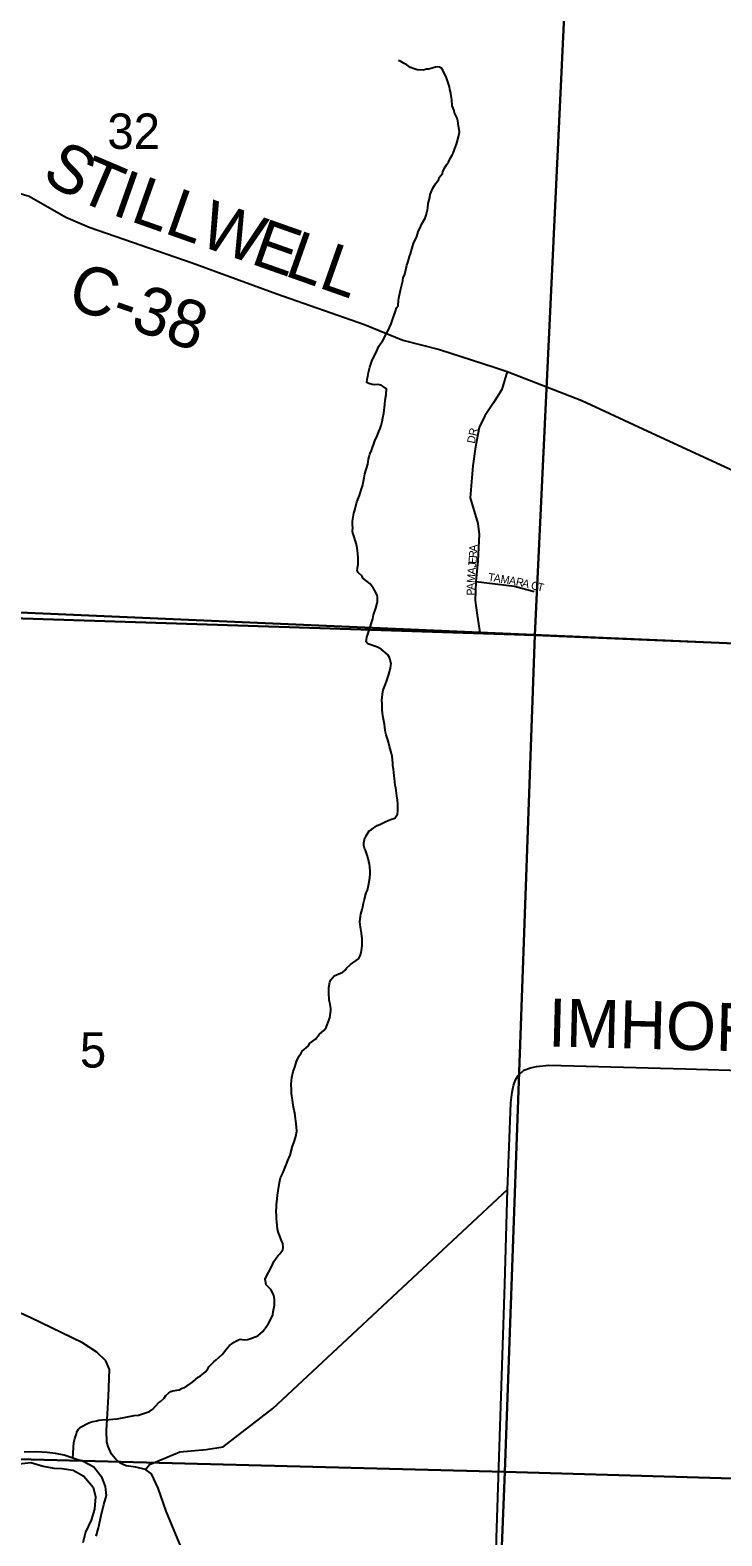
# Model space of a CAD drawing. Extents: x 1310247 to 1552180, y 377264 to 706493.
# Drawn here: x 1322302 to 1326623, y 541170 to 550580 of the extents above; entities that cross this region are included whole.
import ezdxf

# ---------------------------------------------------------------- set-up
doc = ezdxf.new("R2010")
doc.units = 0
for name, color, linetype in [('GM_X_County_Road', 7, 'Continuous'), ('GM_X_County_Road_Text', 7, 'Continuous'), ('GM_X_Major_River', 7, 'Continuous'), ('GM_X_Minor_River', 7, 'Continuous'), ('GM_X_Section', 7, 'Continuous'), ('GM_X_Section_Text', 7, 'Continuous'), ('GM_X_Township', 7, 'Continuous'), ('GM_X_Township_Road', 7, 'Continuous'), ('GM_X_Township_Road_Text', 7, 'Continuous'), ('GM_X_Township_ROW', 7, 'Continuous'), ('GM_X_Township_Subdivision', 7, 'Continuous'), ('GM_X_Township_Subdivision_Text', 7, 'Continuous')]:
    doc.layers.add(name, color=color, linetype=linetype)

msp = doc.modelspace()

# ---------------------------------------------------------------- linework, layer by layer
at = {"layer": 'GM_X_County_Road'}
for points in [[(1322096.4, 549601.3), (1322294.8, 549543.1), (1322525.5, 549411.9), (1322670, 549349.5), (1323313, 549125.9), (1323842.5, 548931.7), (1324390.2, 548741), (1324629.9, 548641.7), (1324858.8, 548584.8), (1325200.3, 548474.4), (1325281.8, 548446.6), (1325748.4, 548265.1), (1326187.6, 548062.2), (1326910.4, 547727.8)], [(1323254.6, 541075.1), (1323210.9, 541178.2), (1323151.5, 541324.3), (1323101.1, 541468.2), (1323059.6, 541557.3), (1323023.4, 541584.4), (1322962.2, 541600), (1322902.3, 541608.1), (1322864.8, 541625.3), (1322834.3, 541652.4), (1322810, 541680.9), (1322788.4, 541727.8), (1322781.7, 541755.6), (1322779.6, 541828.2), (1322785.9, 541931.9), (1322791.1, 542040.8), (1322798.3, 542210.9), (1322775.5, 542263.8), (1322718.5, 542318.8), (1322629.2, 542375.8), (1322306.7, 542533.5), (1321975.8, 542680.7)]]:
    msp.add_lwpolyline(points, dxfattribs=at)
at = {"layer": 'GM_X_Major_River'}
for points in [[(1322713.9, 541169.1), (1322729.3, 541220.9), (1322745.3, 541296.7), (1322763.1, 541366.5), (1322778.5, 541422.3), (1322772, 541478.6), (1322751.3, 541533.3), (1322698.9, 541598.8), (1322633.6, 541634.5), (1322568, 541656.2), (1322514.3, 541673.6), (1322460.5, 541684.9), (1322408.5, 541692.2), (1322340.4, 541695.9), (1322264.2, 541693.8)], [(1322232.2, 541620.3), (1322306.6, 541628.5), (1322382.2, 541606.6), (1322450.1, 541592.9), (1322500.2, 541591.7), (1322570, 541579.9), (1322637.3, 541544.2), (1322695.7, 541474.5), (1322710.2, 541414), (1322704.2, 541337.9), (1322682.4, 541268.2), (1322648.3, 541192.8), (1322630.6, 541127)]]:
    msp.add_lwpolyline(points, dxfattribs=at)
at = {"layer": 'GM_X_Minor_River'}
for points in [[(1324599.7, 548858), (1324602.5, 548892), (1324604.9, 548906), (1324616.1, 548955.9), (1324629.4, 549013.7), (1324631.9, 549033.7), (1324640.3, 549049.5), (1324646.8, 549071.4), (1324653.8, 549111.3), (1324660.2, 549127.2), (1324671.1, 549165.1), (1324677.5, 549182.9), (1324690.6, 549226.8), (1324697.1, 549246.6), (1324716.2, 549290.3), (1324720.6, 549306.2), (1324724.9, 549320.2), (1324741.8, 549355.8), (1324748.1, 549369.7), (1324769, 549405.3), (1324775.5, 549423.2), (1324784.3, 549457), (1324786.6, 549469), (1324787.2, 549497.1), (1324798.2, 549534.9), (1324800.6, 549552.9), (1324817.6, 549592.6), (1324834.3, 549620.2), (1324855, 549647.8), (1324857.3, 549659.8), (1324878, 549685.3), (1324880.2, 549697.3), (1324897, 549727), (1324903.3, 549738.8), (1324915.7, 549754.6), (1324928.4, 549782.3), (1324938.8, 549798.1), (1324943.1, 549812), (1324951.7, 549833.9), (1324964.5, 549867.7), (1324968.8, 549881.6), (1324977.6, 549913.5), (1324984.4, 549945.4), (1324975.6, 549997.8), (1324973.9, 550013.8), (1324968.3, 550030), (1324953, 550062.5), (1324951.3, 550078.6), (1324937.9, 550107), (1324934.8, 550145.2), (1324933.1, 550157.2), (1324929.7, 550183.4), (1324927.9, 550195.5), (1324924.3, 550209.6), (1324920.6, 550225.7), (1324915, 550243.9), (1324907.6, 550270.2), (1324900, 550288.4), (1324892.3, 550302.7), (1324880.7, 550325), (1324871.1, 550343.3), (1324859.2, 550349.6), (1324845.2, 550349.9), (1324833.1, 550348.2), (1324819, 550344.6), (1324792.7, 550337.2), (1324778.6, 550335.5), (1324758.4, 550330), (1324718.3, 550333), (1324700.3, 550337.5), (1324678.4, 550346.1), (1324654.7, 550362.7), (1324638.9, 550371.1), (1324617.1, 550383.7), (1324603.2, 550390.1)], [(1324520.1, 546204.8), (1324514.9, 546243), (1324504.1, 546295.4), (1324500.9, 546331.6), (1324499.8, 546369.7), (1324498.4, 546393.8), (1324505.6, 546447.8), (1324510, 546461.7), (1324520.8, 546493.5), (1324527.2, 546509.4), (1324540.1, 546547.2), (1324553.2, 546593), (1324555.6, 546609), (1324555.9, 546623), (1324550.3, 546643.2), (1324546.7, 546659.4), (1324537, 546675.7), (1324507.5, 546700.4), (1324493.7, 546710.8), (1324471.9, 546723.4), (1324412.1, 546744.9), (1324400.4, 546757.3), (1324405.1, 546787.2), (1324418, 546825), (1324441.9, 546900.6), (1324446.5, 546926.6), (1324461.5, 546968.3), (1324470.2, 546998.2), (1324472.5, 547010.2), (1324471.1, 547036.3), (1324469.4, 547048.3), (1324452.1, 547080.9), (1324444.4, 547095.1), (1324424.9, 547119.6), (1324379.5, 547154.9), (1324375.8, 547167), (1324350.2, 547191.7), (1324344.5, 547203.9), (1324346.8, 547215.8), (1324351.4, 547243.8), (1324350.4, 547283.9), (1324348.9, 547308), (1324347.4, 547328.1), (1324342, 547358.3), (1324334.7, 547386.6), (1324323.4, 547419), (1324317.8, 547437.2), (1324316.1, 547451.2), (1324316.5, 547469.3), (1324315, 547489.4), (1324315.5, 547511.4), (1324317.8, 547523.4), (1324324.7, 547561.3), (1324329.1, 547581.3), (1324342.4, 547633.1), (1324359.4, 547672.8), (1324365.9, 547692.7), (1324372.4, 547714.6), (1324376.8, 547730.5), (1324388, 547782.4), (1324392.6, 547808.3), (1324410.1, 547868), (1324412.4, 547882), (1324414.8, 547898), (1324419.2, 547913.9), (1324423.6, 547929.9), (1324434.2, 547953.7), (1324455.6, 548013.3), (1324468.4, 548045.1), (1324479.1, 548070.9), (1324487.6, 548090.7), (1324494, 548108.6), (1324500.6, 548134.5), (1324505.1, 548156.5), (1324511.9, 548186.4), (1324517.1, 548240.4), (1324519.8, 548268.4), (1324524.6, 548302.4), (1324527.4, 548338.4), (1324507.7, 548352.9), (1324493.8, 548361.3), (1324473.9, 548365.8), (1324453.7, 548364.3), (1324437.7, 548366.7), (1324417.8, 548371.2), (1324403.9, 548377.6), (1324406.4, 548399.6), (1324410.8, 548415.5), (1324415.4, 548441.5), (1324424.1, 548473.3), (1324437.1, 548511.1), (1324466.7, 548576.5), (1324479.4, 548604.3), (1324506.5, 548645.8), (1324525.3, 548679.4), (1324535.8, 548699.2), (1324556.9, 548744.8), (1324565.6, 548770.6), (1324582.9, 548824.3), (1324589.4, 548844.2), (1324599.7, 548858)], [(1323959.8, 543776), (1323954.6, 543814.3), (1323950.9, 543828.4), (1323945.7, 543860.6), (1323940.4, 543894.8), (1323937, 543921), (1323935.3, 543935.1), (1323933.8, 543955.2), (1323932.7, 543993.3), (1323935.7, 544035.4), (1323944.6, 544073.2), (1323955.2, 544099), (1323961.7, 544120.9), (1323966.1, 544134.9), (1323983, 544170.5), (1323993.3, 544182.3), (1324001.7, 544200.2), (1324040.6, 544233.3), (1324047, 544247.2), (1324083.8, 544274.3), (1324106.5, 544303.8), (1324139.3, 544331.1), (1324151.7, 544346.8), (1324156.1, 544364.8), (1324173.2, 544408.5), (1324180.3, 544454.4), (1324180.6, 544466.5), (1324175.2, 544492.7), (1324171.5, 544508.8), (1324169.8, 544520.9), (1324166.7, 544561.1), (1324167.2, 544583.1), (1324167.5, 544597.1), (1324174.4, 544631.1), (1324180.7, 544644.9), (1324201.4, 544670.5), (1324254.1, 544693.3), (1324270.4, 544704.9), (1324278.8, 544718.7), (1324303.4, 544740.2), (1324352.4, 544777), (1324362.9, 544794.8), (1324369.4, 544816.7), (1324371.7, 544828.7), (1324376.5, 544860.7), (1324376.7, 544872.7), (1324375.5, 544904.8), (1324373.7, 544916.9), (1324372.2, 544937), (1324365.1, 544975.3), (1324361.8, 545007.4), (1324364.6, 545043.5), (1324366.9, 545055.4), (1324375.6, 545085.3), (1324380, 545101.2), (1324384.6, 545125.2), (1324389, 545141.1), (1324400.1, 545189), (1324408.5, 545204.8), (1324415.2, 545234.7), (1324424.4, 545282.6), (1324425, 545306.7), (1324425.3, 545320.7), (1324424, 545352.8), (1324422.3, 545366.9), (1324413.1, 545403.2), (1324407.6, 545423.4), (1324396.3, 545455.8), (1324390.5, 545468), (1324386.9, 545484.1), (1324385.3, 545502.2), (1324392, 545532.1), (1324400.4, 545546), (1324419.1, 545575.6), (1324433.4, 545585.2), (1324470.2, 545610.4), (1324486.3, 545616), (1324518.9, 545633.3), (1324539.1, 545640.8), (1324553.3, 545646.4), (1324579.6, 545655.8), (1324596.3, 545681.5), (1324598.8, 545701.5), (1324597.7, 545743.6), (1324596.3, 545767.7), (1324592.9, 545795.9), (1324586, 545844.2), (1324582.4, 545862.3), (1324577.3, 545902.5), (1324575.7, 545920.6), (1324570.6, 545960.9), (1324567.2, 545985), (1324567.5, 545999), (1324562.5, 546043.3), (1324558.9, 546059.4), (1324545.9, 546103.9), (1324540.4, 546130.1), (1324536.8, 546144.2), (1324525.5, 546176.6), (1324521.8, 546192.7), (1324520.1, 546204.8)], [(1322568, 541656.2), (1322575.6, 541754.7), (1322580.2, 541778.7), (1322590.9, 541808.5), (1322593.2, 541820.4), (1322603.6, 541836.2), (1322616, 541850), (1322664.8, 541874.8), (1322678.9, 541880.5), (1322693.1, 541884.2), (1322719.3, 541889.5), (1322731.4, 541893.2), (1322751.6, 541894.7), (1322795.8, 541897.7), (1322817.9, 541899.1), (1322846.1, 541902.4), (1322898.5, 541911.1), (1322951, 541921.9), (1322979.2, 541925.2), (1323047.9, 541947.5), (1323068.4, 541963.1), (1323103.4, 542002.3), (1323115.7, 542010), (1323138.2, 542031.5), (1323148.6, 542047.3), (1323169.1, 542064.9), (1323181.4, 542072.6), (1323193.5, 542076.3), (1323217.7, 542081.7), (1323231.8, 542083.4), (1323252.1, 542092.9), (1323268.3, 542098.5), (1323317.3, 542133.4), (1323352.1, 542162.6), (1323366.3, 542170.3), (1323397, 542195.6), (1323411.5, 542213.3), (1323417.8, 542227.2), (1323448.7, 542258.5), (1323463, 542270.2), (1323501.9, 542303.3), (1323533, 542342.6), (1323547.4, 542360.3), (1323576, 542381.7), (1323590.3, 542389.3), (1323602.5, 542395.1), (1323614.6, 542398.8), (1323626.6, 542398.5), (1323640.6, 542396.1), (1323658.7, 542397.7), (1323674.9, 542401.3), (1323723.5, 542420.1), (1323754.3, 542447.4), (1323783.2, 542484.8), (1323791.5, 542496.7), (1323799.9, 542512.5), (1323816.9, 542552.2), (1323819.4, 542570.2), (1323828.4, 542612.1), (1323828.8, 542630.1), (1323827.2, 542648.2), (1323823.8, 542674.3), (1323804.5, 542710.9), (1323777.1, 542739.7), (1323769.9, 542774), (1323776.3, 542789.8), (1323807.7, 542847.2), (1323818.3, 542871), (1323824.6, 542884.9), (1323849.6, 542920.4), (1323861.9, 542932.1), (1323880.5, 542957.7), (1323882.9, 542971.7), (1323879.5, 542997.9), (1323873.7, 543010), (1323868.1, 543026.2), (1323858.6, 543048.5), (1323852.9, 543064.7), (1323847.4, 543086.9), (1323842.4, 543133.2), (1323840.9, 543153.3), (1323841.4, 543173.3), (1323837.9, 543195.4), (1323840.6, 543227.5), (1323840.9, 543239.5), (1323843.8, 543277.5), (1323846.3, 543299.5), (1323851, 543327.5), (1323860.2, 543379.4), (1323864.9, 543407.4), (1323879.6, 543437.1), (1323900.9, 543488.7), (1323911.6, 543516.5), (1323926.4, 543550.2), (1323939.7, 543606.1), (1323948.2, 543625.9), (1323961.2, 543665.7), (1323968, 543699.6), (1323966.6, 543725.7), (1323961.5, 543764), (1323959.8, 543776)]]:
    msp.add_lwpolyline(points, dxfattribs=at)
at = {"layer": 'GM_X_Section'}
for points in [[(1320349.9, 552243.3), (1325704.6, 552080.5), (1325455.2, 546798.8), (1320142.5, 546971.1)], [(1325704.6, 552080.5), (1331016.4, 551943.3), (1330756.7, 546578.8), (1325455.2, 546798.8)], [(1325455.2, 546798.8), (1325267.1, 541570.4), (1319907.5, 541709.9), (1320142.5, 546971.1)], [(1330756.7, 546578.8), (1330462.3, 541419.2), (1325267.1, 541570.4), (1325455.2, 546798.8)], [(1319907.5, 541709.9), (1325267.1, 541570.4), (1325046.7, 536089.3), (1319682.6, 536279.1)], [(1325267.1, 541570.4), (1330462.3, 541419.2), (1330101.6, 535933.3), (1325046.7, 536089.3)]]:
    msp.add_lwpolyline(points, close=True, dxfattribs=at)
at = {"layer": 'GM_X_Township'}
for points in [[(1329978.5, 546605), (1325109.8, 546816.1), (1321995.7, 546951.1), (1318877.6, 547086.3), (1314816.5, 547262.4), (1315032.4, 552495)], [(1313785.8, 520640.4), (1313963.3, 524640.7), (1314153.8, 529209.1), (1314208.3, 530508.2), (1314346, 533789.5), (1314450.9, 536440.7), (1314451.7, 536483.8), (1314517.5, 538371.8), (1314549.4, 539746.9), (1314757.4, 545143.9), (1314795.6, 546163.4), (1314824.8, 546946.5), (1314816.5, 547262.4), (1318877.6, 547086.3), (1321995.7, 546951.1), (1325109.8, 546816.1), (1329978.5, 546605)]]:
    msp.add_lwpolyline(points, dxfattribs=at)
at = {"layer": 'GM_X_Township_Road'}
msp.add_lwpolyline([(1325187.7, 539694.3), (1325210.3, 539740.3), (1325227.1, 539804.4), (1325219.3, 539921.9), (1325199.9, 540067.9), (1325194.8, 540197.1), (1325211.6, 540380.6), (1325215.4, 541155.8), (1325267.1, 542743.7), (1325282.6, 543335.4), (1325300.2, 543764), (1325304.5, 543877.3), (1325312, 543943.6), (1325320.8, 543984.3), (1325332.7, 544019.3), (1325350.2, 544047.5), (1325385.2, 544080), (1325427.2, 544095), (1325464.7, 544103.8), (1325541.7, 544111.9), (1326394.5, 544088.7), (1327434.4, 544058.7)], dxfattribs=at)
at = {"layer": 'GM_X_Township_ROW'}
msp.add_lwpolyline([(1323023.4, 541584.4), (1323047.2, 541615.6), (1323157.1, 541661.4), (1323236, 541695.4), (1323401.9, 541709.4), (1323507.7, 541727.6), (1323817.1, 541965.6), (1325282.6, 543335.4)], dxfattribs=at)
at = {"layer": 'GM_X_Township_Subdivision'}
for points in [[(1325281.8, 548446.6), (1325248.5, 548334.4), (1325195.3, 548251.5), (1325140.9, 548169.8), (1325106.2, 548096.8), (1325082.7, 547976.8), (1325067.8, 547858), (1325050.5, 547657.6), (1325097.5, 547496.7), (1325106.8, 547428.7), (1325098.8, 547264.1), (1325086.4, 547134.2), (1325081.4, 547014.8), (1325094.4, 546923.8), (1325109.8, 546816.1)], [(1325086.4, 547134.2), (1325327.7, 547104.5), (1325450.2, 547072.3)]]:
    msp.add_lwpolyline(points, dxfattribs=at)

# ---------------------------------------------------------------- texts
at = {"layer": 'GM_X_County_Road_Text'}
for s, rotation, p in [('S', 329.05367, (1322364.3, 549650.2)), ('T', 336.95304, (1322578.1, 549525.7)), ('I', 340.55523, (1322803.7, 549430.3)), ('L', 340.53519, (1322919.9, 549389.3)), ('L', 340.54116, (1323131.5, 549314.6)), ('W', 340.54094, (1323343.1, 549239.8)), ('E', 340.54133, (1323670.8, 549124)), ('L', 340.54012, (1323882.4, 549049.3)), ('L', 340.54497, (1324094, 548974.5)), ('C-38', 340.72513, (1322520.3, 548855.8))]:
    msp.add_text(s, height=300, rotation=rotation, dxfattribs=at).set_placement(p)
at = {"layer": 'GM_X_Section_Text'}
for s, p in [('32', (1322784.3, 549838.1)), ('5', (1322612.7, 544096.7))]:
    msp.add_text(s, height=221, rotation=0.00001, dxfattribs=at).set_placement(p)
at = {"layer": 'GM_X_Township_Road_Text'}
msp.add_text('IMHOFF', height=300, rotation=358.54592, dxfattribs=at).set_placement((1325535.1, 544229.2))
at = {"layer": 'GM_X_Township_Subdivision_Text'}
for s, rotation, p in [('DR', 78.11279, (1325078.5, 547993.9)), ('R', 87.46715, (1325091.9, 547280.3)), ('A', 87.71287, (1325093.7, 547320.1)), ('A', 84.36334, (1325082.5, 547176.6)), ('J', 84.35031, (1325086.9, 547220.3)), ('E', 85.6294, (1325089.1, 547243.5)), ('A', 89.56279, (1325078.4, 547081.1)), ('M', 85.78168, (1325078.7, 547124.2)), ('T', 351.2232, (1325159.6, 547138.9)), ('A', 351.21771, (1325194.3, 547133.5)), ('M', 351.22303, (1325237.8, 547126.8)), ('A', 350.40383, (1325289.8, 547118.8)), ('R', 347.14326, (1325332.5, 547111.6)), ('A', 346.31958, (1325370.9, 547102.8)), ('C', 346.29433, (1325426.4, 547089.3)), ('T', 346.29175, (1325464.9, 547079.9)), ('P', 89.89753, (1325078.3, 547046))]:
    msp.add_text(s, height=50, rotation=rotation, dxfattribs=at).set_placement(p)

doc.saveas('drawing.dxf')
